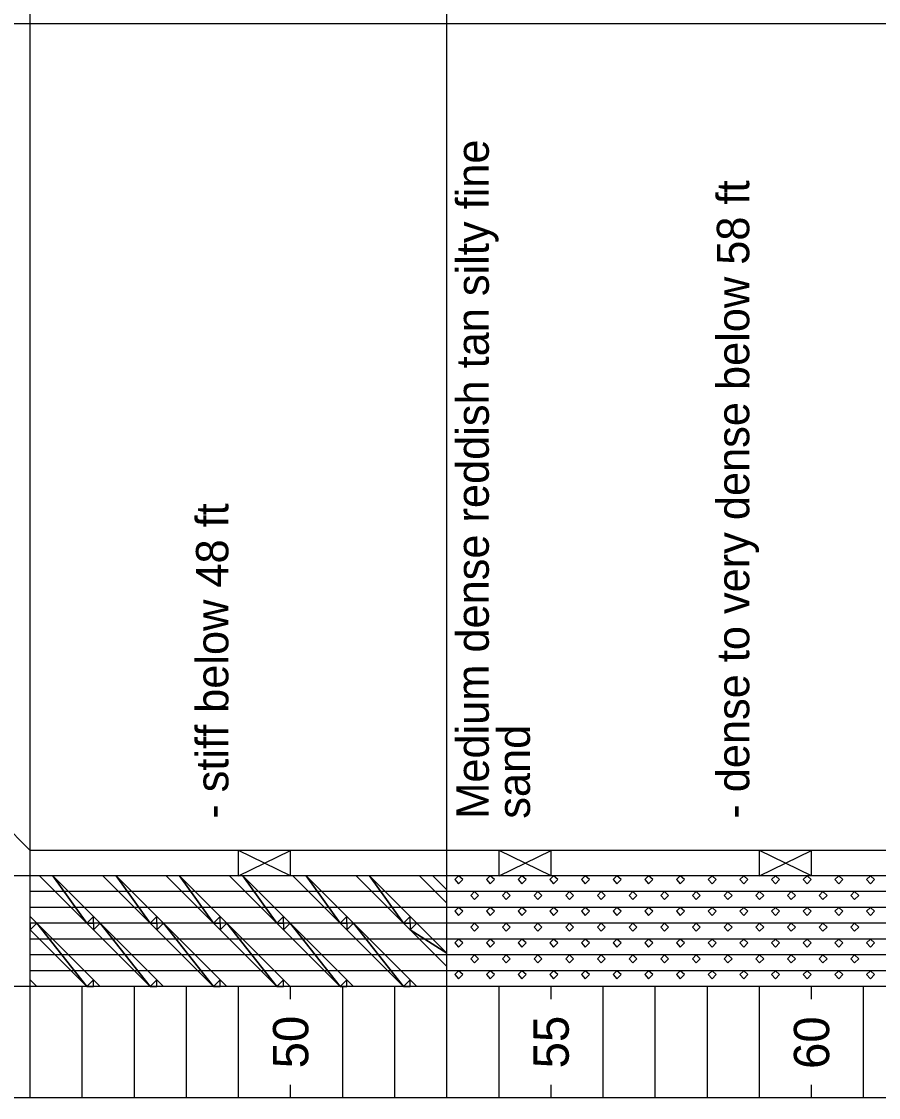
# Model space of a CAD drawing. Extents: x 1313964 to 1316843, y 2087046 to 2096619.
# Drawn here: x 1313989.21 to 1314005.66, y 2089873.43 to 2089894.09 of the extents above; entities that cross this region are included whole.
import ezdxf

# ---------------------------------------------------------------- set-up
doc = ezdxf.new("R2010")
doc.units = 0
doc.layers.add('B-Sub-Contour', color=7, linetype='Continuous')

msp = doc.modelspace()

# ---------------------------------------------------------------- linework, layer by layer
at = {"layer": 'B-Sub-Contour'}
for points in [[(1314036.804, 2089873.434), (1314036.804, 2089916.306), (1313975.385, 2089916.306), (1313975.385, 2089873.434), (1314036.804, 2089873.434)], [(1313989.372, 2089873.434), (1313989.372, 2089916.306)], [(1313997.372, 2089894.049), (1313997.372, 2089914.481)], [(1314034.372, 2089894.049), (1313982.683, 2089894.049)], [(1313997.372, 2089878.178), (1313997.372, 2089894.049)], [(1313989.372, 2089878.178), (1313988.824, 2089878.725)], [(1314034.372, 2089878.178), (1313989.372, 2089878.178)], [(1313993.372, 2089877.691), (1313994.372, 2089878.178)], [(1313994.372, 2089877.691), (1313993.372, 2089878.178)], [(1313993.372, 2089877.691), (1313993.372, 2089878.178)], [(1313994.372, 2089877.691), (1313994.372, 2089878.178)], [(1313997.372, 2089877.691), (1313997.372, 2089878.178)], [(1313998.372, 2089877.691), (1313999.372, 2089878.178)], [(1313999.372, 2089877.691), (1313998.372, 2089878.178)], [(1313998.372, 2089877.691), (1313998.372, 2089878.178)], [(1313999.372, 2089877.691), (1313999.372, 2089878.178)], [(1314003.372, 2089877.691), (1314004.372, 2089878.178)], [(1314004.372, 2089877.691), (1314003.372, 2089878.178)], [(1314003.372, 2089877.691), (1314003.372, 2089878.178)], [(1314004.372, 2089877.691), (1314004.372, 2089878.178)], [(1314034.372, 2089877.691), (1313982.683, 2089877.691)], [(1313997.372, 2089875.563), (1313997.372, 2089877.691)], [(1313997.372, 2089877.387), (1313989.372, 2089877.387)], [(1314022.372, 2089877.387), (1313997.372, 2089877.387)], [(1313997.372, 2089877.083), (1313989.372, 2089877.083)], [(1314022.372, 2089877.083), (1313997.372, 2089877.083)], [(1313997.372, 2089876.779), (1313989.372, 2089876.779)], [(1314022.372, 2089876.779), (1313997.372, 2089876.779)], [(1313997.372, 2089876.475), (1313989.372, 2089876.475)], [(1314022.372, 2089876.475), (1313997.372, 2089876.475)], [(1313997.372, 2089876.171), (1313989.372, 2089876.171)], [(1314022.372, 2089876.171), (1313997.372, 2089876.171)], [(1313997.372, 2089875.867), (1313989.372, 2089875.867)], [(1314022.372, 2089875.867), (1313997.372, 2089875.867)], [(1314034.372, 2089875.563), (1313982.683, 2089875.563)], [(1313989.372, 2089875.319), (1313989.372, 2089875.563)], [(1313990.372, 2089873.434), (1313990.372, 2089875.563)], [(1313990.372, 2089873.434), (1313990.372, 2089875.563)], [(1313991.372, 2089873.434), (1313991.372, 2089875.563)], [(1313992.372, 2089873.434), (1313992.372, 2089875.563)], [(1313992.372, 2089873.434), (1313992.372, 2089875.563)], [(1313993.372, 2089873.434), (1313993.372, 2089875.563)], [(1313994.372, 2089875.319), (1313994.372, 2089875.563)], [(1313994.372, 2089875.319), (1313994.372, 2089875.563)], [(1313995.372, 2089873.434), (1313995.372, 2089875.563)], [(1313996.372, 2089873.434), (1313996.372, 2089875.563)], [(1313996.372, 2089873.434), (1313996.372, 2089875.563)], [(1313997.372, 2089873.434), (1313997.372, 2089875.563)], [(1313998.372, 2089873.434), (1313998.372, 2089875.563)], [(1313998.372, 2089873.434), (1313998.372, 2089875.563)], [(1313999.372, 2089875.319), (1313999.372, 2089875.563)], [(1314000.372, 2089873.434), (1314000.372, 2089875.563)], [(1314000.372, 2089873.434), (1314000.372, 2089875.563)], [(1314001.372, 2089873.434), (1314001.372, 2089875.563)], [(1314002.372, 2089873.434), (1314002.372, 2089875.563)], [(1314002.372, 2089873.434), (1314002.372, 2089875.563)], [(1314003.372, 2089873.434), (1314003.372, 2089875.563)], [(1314004.372, 2089875.319), (1314004.372, 2089875.563)], [(1314004.372, 2089875.319), (1314004.372, 2089875.563)], [(1314005.372, 2089873.434), (1314005.372, 2089875.563)], [(1313989.372, 2089873.434), (1313989.372, 2089873.678)], [(1313994.372, 2089873.434), (1313994.372, 2089873.678)], [(1313994.372, 2089873.434), (1313994.372, 2089873.678)], [(1313999.372, 2089873.434), (1313999.372, 2089873.678)], [(1314004.372, 2089873.434), (1314004.372, 2089873.678)], [(1314004.372, 2089873.434), (1314004.372, 2089873.678)]]:
    msp.add_lwpolyline(points, dxfattribs=at)
for points in [[(1313990.46, 2089876.779), (1313989.803, 2089877.691), (1313989.548, 2089877.691), (1313990.46, 2089876.779)], [(1313990.46, 2089876.779), (1313990.588, 2089876.907), (1313989.803, 2089877.691), (1313990.46, 2089876.779)], [(1313991.676, 2089876.779), (1313991.02, 2089877.691), (1313990.764, 2089877.691), (1313991.676, 2089876.779)], [(1313991.676, 2089876.779), (1313991.804, 2089876.907), (1313991.02, 2089877.691), (1313991.676, 2089876.779)], [(1313992.893, 2089876.779), (1313992.236, 2089877.691), (1313991.98, 2089877.691), (1313992.893, 2089876.779)], [(1313992.893, 2089876.779), (1313993.02, 2089876.907), (1313992.236, 2089877.691), (1313992.893, 2089876.779)], [(1313994.109, 2089876.779), (1313993.452, 2089877.691), (1313993.197, 2089877.691), (1313994.109, 2089876.779)], [(1313994.109, 2089876.779), (1313994.237, 2089876.907), (1313993.452, 2089877.691), (1313994.109, 2089876.779)], [(1313995.325, 2089876.779), (1313994.668, 2089877.691), (1313994.413, 2089877.691), (1313995.325, 2089876.779)], [(1313995.325, 2089876.779), (1313995.453, 2089876.907), (1313994.668, 2089877.691), (1313995.325, 2089876.779)], [(1313996.541, 2089876.779), (1313995.885, 2089877.691), (1313995.629, 2089877.691), (1313996.541, 2089876.779)], [(1313996.541, 2089876.779), (1313996.669, 2089876.907), (1313995.885, 2089877.691), (1313996.541, 2089876.779)], [(1313997.101, 2089877.691), (1313996.845, 2089877.691), (1313997.372, 2089877.165), (1313997.372, 2089877.42)], [(1313997.597, 2089877.691), (1313997.524, 2089877.618), (1313997.597, 2089877.539), (1313997.676, 2089877.618)], [(1313998.205, 2089877.691), (1313998.132, 2089877.618), (1313998.205, 2089877.539), (1313998.284, 2089877.618)], [(1313998.813, 2089877.691), (1313998.74, 2089877.618), (1313998.813, 2089877.539), (1313998.892, 2089877.618)], [(1313999.421, 2089877.691), (1313999.348, 2089877.618), (1313999.421, 2089877.539), (1313999.5, 2089877.618)], [(1314000.029, 2089877.691), (1313999.956, 2089877.618), (1314000.029, 2089877.539), (1314000.108, 2089877.618)], [(1314000.637, 2089877.691), (1314000.564, 2089877.618), (1314000.637, 2089877.539), (1314000.716, 2089877.618)], [(1314001.245, 2089877.691), (1314001.172, 2089877.618), (1314001.245, 2089877.539), (1314001.324, 2089877.618)], [(1314001.853, 2089877.691), (1314001.78, 2089877.618), (1314001.853, 2089877.539), (1314001.932, 2089877.618)], [(1314002.462, 2089877.691), (1314002.389, 2089877.618), (1314002.462, 2089877.539), (1314002.541, 2089877.618)], [(1314003.07, 2089877.691), (1314002.997, 2089877.618), (1314003.07, 2089877.539), (1314003.149, 2089877.618)], [(1314003.678, 2089877.691), (1314003.605, 2089877.618), (1314003.678, 2089877.539), (1314003.757, 2089877.618)], [(1314004.286, 2089877.691), (1314004.213, 2089877.618), (1314004.286, 2089877.539), (1314004.365, 2089877.618)], [(1314004.894, 2089877.691), (1314004.821, 2089877.618), (1314004.894, 2089877.539), (1314004.973, 2089877.618)], [(1314005.502, 2089877.691), (1314005.429, 2089877.618), (1314005.502, 2089877.539), (1314005.581, 2089877.618)], [(1313997.901, 2089877.387), (1313997.828, 2089877.314), (1313997.901, 2089877.235), (1313997.98, 2089877.314)], [(1313998.509, 2089877.387), (1313998.436, 2089877.314), (1313998.509, 2089877.235), (1313998.588, 2089877.314)], [(1313999.117, 2089877.387), (1313999.044, 2089877.314), (1313999.117, 2089877.235), (1313999.196, 2089877.314)], [(1313999.725, 2089877.387), (1313999.652, 2089877.314), (1313999.725, 2089877.235), (1313999.804, 2089877.314)], [(1314000.333, 2089877.387), (1314000.26, 2089877.314), (1314000.333, 2089877.235), (1314000.412, 2089877.314)], [(1314000.941, 2089877.387), (1314000.868, 2089877.314), (1314000.941, 2089877.235), (1314001.02, 2089877.314)], [(1314001.549, 2089877.387), (1314001.476, 2089877.314), (1314001.549, 2089877.235), (1314001.628, 2089877.314)], [(1314002.157, 2089877.387), (1314002.085, 2089877.314), (1314002.157, 2089877.235), (1314002.237, 2089877.314)], [(1314002.766, 2089877.387), (1314002.693, 2089877.314), (1314002.766, 2089877.235), (1314002.845, 2089877.314)], [(1314003.374, 2089877.387), (1314003.301, 2089877.314), (1314003.374, 2089877.235), (1314003.453, 2089877.314)], [(1314003.982, 2089877.387), (1314003.909, 2089877.314), (1314003.982, 2089877.235), (1314004.061, 2089877.314)], [(1314004.59, 2089877.387), (1314004.517, 2089877.314), (1314004.59, 2089877.235), (1314004.669, 2089877.314)], [(1314005.198, 2089877.387), (1314005.125, 2089877.314), (1314005.198, 2089877.235), (1314005.277, 2089877.314)], [(1313997.597, 2089877.083), (1313997.524, 2089877.01), (1313997.597, 2089876.931), (1313997.676, 2089877.01)], [(1313998.205, 2089877.083), (1313998.132, 2089877.01), (1313998.205, 2089876.931), (1313998.284, 2089877.01)], [(1313998.813, 2089877.083), (1313998.74, 2089877.01), (1313998.813, 2089876.931), (1313998.892, 2089877.01)], [(1313999.421, 2089877.083), (1313999.348, 2089877.01), (1313999.421, 2089876.931), (1313999.5, 2089877.01)], [(1314000.029, 2089877.083), (1313999.956, 2089877.01), (1314000.029, 2089876.931), (1314000.108, 2089877.01)], [(1314000.637, 2089877.083), (1314000.564, 2089877.01), (1314000.637, 2089876.931), (1314000.716, 2089877.01)], [(1314001.245, 2089877.083), (1314001.172, 2089877.01), (1314001.245, 2089876.931), (1314001.324, 2089877.01)], [(1314001.853, 2089877.083), (1314001.78, 2089877.01), (1314001.853, 2089876.931), (1314001.932, 2089877.01)], [(1314002.462, 2089877.083), (1314002.389, 2089877.01), (1314002.462, 2089876.931), (1314002.541, 2089877.01)], [(1314003.07, 2089877.083), (1314002.997, 2089877.01), (1314003.07, 2089876.931), (1314003.149, 2089877.01)], [(1314003.678, 2089877.083), (1314003.605, 2089877.01), (1314003.678, 2089876.931), (1314003.757, 2089877.01)], [(1314004.286, 2089877.083), (1314004.213, 2089877.01), (1314004.286, 2089876.931), (1314004.365, 2089877.01)], [(1314004.894, 2089877.083), (1314004.821, 2089877.01), (1314004.894, 2089876.931), (1314004.973, 2089877.01)], [(1314005.502, 2089877.083), (1314005.429, 2089877.01), (1314005.502, 2089876.931), (1314005.581, 2089877.01)], [(1313989.499, 2089876.779), (1313989.372, 2089876.779), (1313989.372, 2089876.907), (1313989.499, 2089876.779)], [(1313990.46, 2089876.779), (1313990.588, 2089876.779), (1313990.588, 2089876.907), (1313990.46, 2089876.779)], [(1313990.716, 2089876.779), (1313990.588, 2089876.779), (1313990.588, 2089876.907), (1313990.716, 2089876.779)], [(1313991.676, 2089876.779), (1313991.804, 2089876.779), (1313991.804, 2089876.907), (1313991.676, 2089876.779)], [(1313991.932, 2089876.779), (1313991.804, 2089876.779), (1313991.804, 2089876.907), (1313991.932, 2089876.779)], [(1313992.893, 2089876.779), (1313993.02, 2089876.779), (1313993.02, 2089876.907), (1313992.893, 2089876.779)], [(1313993.148, 2089876.779), (1313993.02, 2089876.779), (1313993.02, 2089876.907), (1313993.148, 2089876.779)], [(1313994.109, 2089876.779), (1313994.237, 2089876.779), (1313994.237, 2089876.907), (1313994.109, 2089876.779)], [(1313994.364, 2089876.779), (1313994.237, 2089876.779), (1313994.237, 2089876.907), (1313994.364, 2089876.779)], [(1313995.325, 2089876.779), (1313995.453, 2089876.779), (1313995.453, 2089876.907), (1313995.325, 2089876.779)], [(1313995.58, 2089876.779), (1313995.453, 2089876.779), (1313995.453, 2089876.907), (1313995.58, 2089876.779)], [(1313996.541, 2089876.779), (1313996.669, 2089876.779), (1313996.669, 2089876.907), (1313996.541, 2089876.779)], [(1313996.797, 2089876.779), (1313996.669, 2089876.779), (1313996.669, 2089876.907), (1313996.797, 2089876.779)], [(1313989.499, 2089876.779), (1313989.372, 2089876.779), (1313989.372, 2089876.651), (1313989.499, 2089876.779)], [(1313990.46, 2089875.563), (1313989.499, 2089876.779), (1313989.372, 2089876.651), (1313990.46, 2089875.563)], [(1313990.46, 2089875.563), (1313990.588, 2089875.69), (1313989.499, 2089876.779), (1313990.46, 2089875.563)], [(1313990.588, 2089876.779), (1313990.588, 2089876.651), (1313990.46, 2089876.779), (1313990.588, 2089876.779)], [(1313990.716, 2089876.779), (1313990.588, 2089876.779), (1313990.588, 2089876.651), (1313990.716, 2089876.779)], [(1313991.676, 2089875.563), (1313990.716, 2089876.779), (1313990.588, 2089876.651), (1313991.676, 2089875.563)], [(1313991.676, 2089875.563), (1313991.804, 2089875.69), (1313990.716, 2089876.779), (1313991.676, 2089875.563)], [(1313991.804, 2089876.779), (1313991.804, 2089876.651), (1313991.676, 2089876.779), (1313991.804, 2089876.779)], [(1313991.932, 2089876.779), (1313991.804, 2089876.779), (1313991.804, 2089876.651), (1313991.932, 2089876.779)], [(1313992.893, 2089875.563), (1313991.932, 2089876.779), (1313991.804, 2089876.651), (1313992.893, 2089875.563)], [(1313992.893, 2089875.563), (1313993.02, 2089875.69), (1313991.932, 2089876.779), (1313992.893, 2089875.563)], [(1313993.02, 2089876.779), (1313993.02, 2089876.651), (1313992.893, 2089876.779), (1313993.02, 2089876.779)], [(1313993.148, 2089876.779), (1313993.02, 2089876.779), (1313993.02, 2089876.651), (1313993.148, 2089876.779)], [(1313994.109, 2089875.563), (1313993.148, 2089876.779), (1313993.02, 2089876.651), (1313994.109, 2089875.563)], [(1313994.109, 2089875.563), (1313994.237, 2089875.69), (1313993.148, 2089876.779), (1313994.109, 2089875.563)], [(1313994.237, 2089876.779), (1313994.237, 2089876.651), (1313994.109, 2089876.779), (1313994.237, 2089876.779)], [(1313994.364, 2089876.779), (1313994.237, 2089876.779), (1313994.237, 2089876.651), (1313994.364, 2089876.779)], [(1313995.325, 2089875.563), (1313994.364, 2089876.779), (1313994.237, 2089876.651), (1313995.325, 2089875.563)], [(1313995.325, 2089875.563), (1313995.453, 2089875.69), (1313994.364, 2089876.779), (1313995.325, 2089875.563)], [(1313995.453, 2089876.779), (1313995.453, 2089876.651), (1313995.325, 2089876.779), (1313995.453, 2089876.779)], [(1313995.58, 2089876.779), (1313995.453, 2089876.779), (1313995.453, 2089876.651), (1313995.58, 2089876.779)], [(1313996.541, 2089875.563), (1313995.58, 2089876.779), (1313995.453, 2089876.651), (1313996.541, 2089875.563)], [(1313996.541, 2089875.563), (1313996.669, 2089875.69), (1313995.58, 2089876.779), (1313996.541, 2089875.563)], [(1313996.669, 2089876.779), (1313996.669, 2089876.651), (1313996.541, 2089876.779), (1313996.669, 2089876.779)], [(1313996.797, 2089876.779), (1313996.669, 2089876.779), (1313996.669, 2089876.651), (1313996.797, 2089876.779)], [(1313996.669, 2089876.651), (1313997.372, 2089876.204), (1313996.797, 2089876.779), (1313996.669, 2089876.651)], [(1313996.669, 2089876.651), (1313997.372, 2089875.949), (1313997.372, 2089876.204), (1313996.669, 2089876.651)], [(1313997.901, 2089876.779), (1313997.828, 2089876.706), (1313997.901, 2089876.627), (1313997.98, 2089876.706)], [(1313998.509, 2089876.779), (1313998.436, 2089876.706), (1313998.509, 2089876.627), (1313998.588, 2089876.706)], [(1313999.117, 2089876.779), (1313999.044, 2089876.706), (1313999.117, 2089876.627), (1313999.196, 2089876.706)], [(1313999.725, 2089876.779), (1313999.652, 2089876.706), (1313999.725, 2089876.627), (1313999.804, 2089876.706)], [(1314000.333, 2089876.779), (1314000.26, 2089876.706), (1314000.333, 2089876.627), (1314000.412, 2089876.706)], [(1314000.941, 2089876.779), (1314000.868, 2089876.706), (1314000.941, 2089876.627), (1314001.02, 2089876.706)], [(1314001.549, 2089876.779), (1314001.476, 2089876.706), (1314001.549, 2089876.627), (1314001.628, 2089876.706)], [(1314002.157, 2089876.779), (1314002.085, 2089876.706), (1314002.157, 2089876.627), (1314002.237, 2089876.706)], [(1314002.766, 2089876.779), (1314002.693, 2089876.706), (1314002.766, 2089876.627), (1314002.845, 2089876.706)], [(1314003.374, 2089876.779), (1314003.301, 2089876.706), (1314003.374, 2089876.627), (1314003.453, 2089876.706)], [(1314003.982, 2089876.779), (1314003.909, 2089876.706), (1314003.982, 2089876.627), (1314004.061, 2089876.706)], [(1314004.59, 2089876.779), (1314004.517, 2089876.706), (1314004.59, 2089876.627), (1314004.669, 2089876.706)], [(1314005.198, 2089876.779), (1314005.125, 2089876.706), (1314005.198, 2089876.627), (1314005.277, 2089876.706)], [(1313997.597, 2089876.475), (1313997.524, 2089876.402), (1313997.597, 2089876.323), (1313997.676, 2089876.402)], [(1313998.205, 2089876.475), (1313998.132, 2089876.402), (1313998.205, 2089876.323), (1313998.284, 2089876.402)], [(1313998.813, 2089876.475), (1313998.74, 2089876.402), (1313998.813, 2089876.323), (1313998.892, 2089876.402)], [(1313999.421, 2089876.475), (1313999.348, 2089876.402), (1313999.421, 2089876.323), (1313999.5, 2089876.402)], [(1314000.029, 2089876.475), (1313999.956, 2089876.402), (1314000.029, 2089876.323), (1314000.108, 2089876.402)], [(1314000.637, 2089876.475), (1314000.564, 2089876.402), (1314000.637, 2089876.323), (1314000.716, 2089876.402)], [(1314001.245, 2089876.475), (1314001.172, 2089876.402), (1314001.245, 2089876.323), (1314001.324, 2089876.402)], [(1314001.853, 2089876.475), (1314001.78, 2089876.402), (1314001.853, 2089876.323), (1314001.932, 2089876.402)], [(1314002.462, 2089876.475), (1314002.389, 2089876.402), (1314002.462, 2089876.323), (1314002.541, 2089876.402)], [(1314003.07, 2089876.475), (1314002.997, 2089876.402), (1314003.07, 2089876.323), (1314003.149, 2089876.402)], [(1314003.678, 2089876.475), (1314003.605, 2089876.402), (1314003.678, 2089876.323), (1314003.757, 2089876.402)], [(1314004.286, 2089876.475), (1314004.213, 2089876.402), (1314004.286, 2089876.323), (1314004.365, 2089876.402)], [(1314004.894, 2089876.475), (1314004.821, 2089876.402), (1314004.894, 2089876.323), (1314004.973, 2089876.402)], [(1314005.502, 2089876.475), (1314005.429, 2089876.402), (1314005.502, 2089876.323), (1314005.581, 2089876.402)], [(1313997.901, 2089876.171), (1313997.828, 2089876.098), (1313997.901, 2089876.019), (1313997.98, 2089876.098)], [(1313998.509, 2089876.171), (1313998.436, 2089876.098), (1313998.509, 2089876.019), (1313998.588, 2089876.098)], [(1313999.117, 2089876.171), (1313999.044, 2089876.098), (1313999.117, 2089876.019), (1313999.196, 2089876.098)], [(1313999.725, 2089876.171), (1313999.652, 2089876.098), (1313999.725, 2089876.019), (1313999.804, 2089876.098)], [(1314000.333, 2089876.171), (1314000.26, 2089876.098), (1314000.333, 2089876.019), (1314000.412, 2089876.098)], [(1314000.941, 2089876.171), (1314000.868, 2089876.098), (1314000.941, 2089876.019), (1314001.02, 2089876.098)], [(1314001.549, 2089876.171), (1314001.476, 2089876.098), (1314001.549, 2089876.019), (1314001.628, 2089876.098)], [(1314002.157, 2089876.171), (1314002.085, 2089876.098), (1314002.157, 2089876.019), (1314002.237, 2089876.098)], [(1314002.766, 2089876.171), (1314002.693, 2089876.098), (1314002.766, 2089876.019), (1314002.845, 2089876.098)], [(1314003.374, 2089876.171), (1314003.301, 2089876.098), (1314003.374, 2089876.019), (1314003.453, 2089876.098)], [(1314003.982, 2089876.171), (1314003.909, 2089876.098), (1314003.982, 2089876.019), (1314004.061, 2089876.098)], [(1314004.59, 2089876.171), (1314004.517, 2089876.098), (1314004.59, 2089876.019), (1314004.669, 2089876.098)], [(1314005.198, 2089876.171), (1314005.125, 2089876.098), (1314005.198, 2089876.019), (1314005.277, 2089876.098)], [(1313997.597, 2089875.867), (1313997.524, 2089875.794), (1313997.597, 2089875.715), (1313997.676, 2089875.794)], [(1313998.205, 2089875.867), (1313998.132, 2089875.794), (1313998.205, 2089875.715), (1313998.284, 2089875.794)], [(1313998.813, 2089875.867), (1313998.74, 2089875.794), (1313998.813, 2089875.715), (1313998.892, 2089875.794)], [(1313999.421, 2089875.867), (1313999.348, 2089875.794), (1313999.421, 2089875.715), (1313999.5, 2089875.794)], [(1314000.029, 2089875.867), (1313999.956, 2089875.794), (1314000.029, 2089875.715), (1314000.108, 2089875.794)], [(1314000.637, 2089875.867), (1314000.564, 2089875.794), (1314000.637, 2089875.715), (1314000.716, 2089875.794)], [(1314001.245, 2089875.867), (1314001.172, 2089875.794), (1314001.245, 2089875.715), (1314001.324, 2089875.794)], [(1314001.853, 2089875.867), (1314001.78, 2089875.794), (1314001.853, 2089875.715), (1314001.932, 2089875.794)], [(1314002.462, 2089875.867), (1314002.389, 2089875.794), (1314002.462, 2089875.715), (1314002.541, 2089875.794)], [(1314003.07, 2089875.867), (1314002.997, 2089875.794), (1314003.07, 2089875.715), (1314003.149, 2089875.794)], [(1314003.678, 2089875.867), (1314003.605, 2089875.794), (1314003.678, 2089875.715), (1314003.757, 2089875.794)], [(1314004.286, 2089875.867), (1314004.213, 2089875.794), (1314004.286, 2089875.715), (1314004.365, 2089875.794)], [(1314004.894, 2089875.867), (1314004.821, 2089875.794), (1314004.894, 2089875.715), (1314004.973, 2089875.794)], [(1314005.502, 2089875.867), (1314005.429, 2089875.794), (1314005.502, 2089875.715), (1314005.581, 2089875.794)], [(1313989.499, 2089875.563), (1313989.372, 2089875.563), (1313989.372, 2089875.69), (1313989.499, 2089875.563)], [(1313990.46, 2089875.563), (1313990.588, 2089875.563), (1313990.588, 2089875.69), (1313990.46, 2089875.563)], [(1313990.716, 2089875.563), (1313990.588, 2089875.563), (1313990.588, 2089875.69), (1313990.716, 2089875.563)], [(1313991.676, 2089875.563), (1313991.804, 2089875.563), (1313991.804, 2089875.69), (1313991.676, 2089875.563)], [(1313991.932, 2089875.563), (1313991.804, 2089875.563), (1313991.804, 2089875.69), (1313991.932, 2089875.563)], [(1313992.893, 2089875.563), (1313993.02, 2089875.563), (1313993.02, 2089875.69), (1313992.893, 2089875.563)], [(1313993.148, 2089875.563), (1313993.02, 2089875.563), (1313993.02, 2089875.69), (1313993.148, 2089875.563)], [(1313994.109, 2089875.563), (1313994.237, 2089875.563), (1313994.237, 2089875.69), (1313994.109, 2089875.563)], [(1313994.364, 2089875.563), (1313994.237, 2089875.563), (1313994.237, 2089875.69), (1313994.364, 2089875.563)], [(1313995.325, 2089875.563), (1313995.453, 2089875.563), (1313995.453, 2089875.69), (1313995.325, 2089875.563)], [(1313995.58, 2089875.563), (1313995.453, 2089875.563), (1313995.453, 2089875.69), (1313995.58, 2089875.563)], [(1313996.541, 2089875.563), (1313996.669, 2089875.563), (1313996.669, 2089875.69), (1313996.541, 2089875.563)], [(1313996.797, 2089875.563), (1313996.669, 2089875.563), (1313996.669, 2089875.69), (1313996.797, 2089875.563)]]:
    msp.add_lwpolyline(points, close=True, dxfattribs=at)

# ---------------------------------------------------------------- texts
for s, height, p in [('Medium dense reddish tan silty fine', 0.62209, (1313998.176, 2089878.786)), ('- dense to very dense below 58 ft', 0.62209, (1314003.176, 2089878.786)), ('- stiff below 48 ft', 0.62209, (1313993.176, 2089878.786)), ('sand', 0.6221, (1313998.966, 2089878.786)), ('50', 0.6786, (1313994.711, 2089873.994)), ('50', 0.6786, (1313994.711, 2089873.994)), ('55', 0.6786, (1313999.711, 2089873.994)), ('60', 0.6786, (1314004.711, 2089873.982)), ('60', 0.6786, (1314004.711, 2089873.982))]:
    msp.add_text(s, height=height, rotation=90, dxfattribs=at).set_placement(p)

doc.saveas('drawing.dxf')
